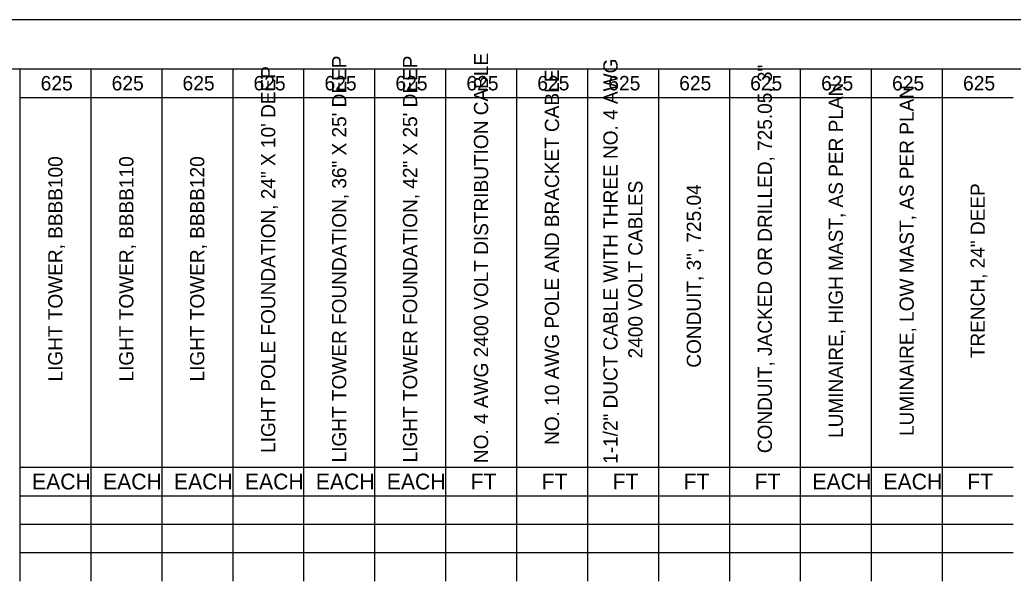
# Model space of a CAD drawing. Extents: x 0 to 34, y 0 to 22.
# Drawn here: x 13.2 to 23.33, y 16.28 to 22 of the extents above; entities that cross this region are included whole.
import ezdxf

# ---------------------------------------------------------------- set-up
doc = ezdxf.new("R2010")
doc.units = 0
for name, color, linetype in [('Default', 7, 'Continuous'), ('SH_Border', 7, 'Continuous'), ('SH_Cut_Line', 7, 'Continuous')]:
    doc.layers.add(name, color=color, linetype=linetype)

msp = doc.modelspace()

# ---------------------------------------------------------------- linework, layer by layer
at = {"layer": 'Default'}
for p, q in [((13.2, 21.5), (13.924, 21.5)), ((13.2, 21.5), (13.2, 21.21)), ((13.924, 21.5), (14.647, 21.5)), ((13.924, 21.5), (13.924, 21.21)), ((14.647, 21.5), (15.371, 21.5)), ((14.647, 21.5), (14.647, 21.21)), ((15.371, 21.5), (16.818, 21.5)), ((15.371, 21.5), (15.371, 21.21)), ((16.094, 21.5), (16.094, 21.21)), ((16.818, 21.5), (23.33, 21.5)), ((16.818, 21.5), (16.818, 21.21)), ((17.541, 21.5), (17.541, 21.21)), ((18.265, 21.5), (18.265, 21.21)), ((18.989, 21.5), (18.989, 21.21)), ((19.712, 21.5), (19.712, 21.21)), ((20.436, 21.5), (20.436, 21.21)), ((21.159, 21.5), (21.159, 21.21)), ((21.883, 21.5), (21.883, 21.21)), ((22.606, 21.5), (22.606, 21.21)), ((13.2, 21.21), (13.924, 21.21)), ((13.2, 21.21), (13.2, 20.92)), ((13.924, 21.21), (14.647, 21.21)), ((13.924, 21.21), (13.924, 20.92)), ((14.647, 21.21), (15.371, 21.21)), ((14.647, 21.21), (14.647, 20.92)), ((15.371, 21.21), (16.818, 21.21)), ((15.371, 21.21), (15.371, 20.92)), ((16.094, 21.21), (16.094, 20.92)), ((16.818, 21.21), (23.33, 21.21)), ((16.818, 21.21), (16.818, 20.92)), ((17.541, 21.21), (17.541, 20.92)), ((18.265, 21.21), (18.265, 20.92)), ((18.989, 21.21), (18.989, 20.92)), ((19.712, 21.21), (19.712, 20.92)), ((20.436, 21.21), (20.436, 20.92)), ((21.159, 21.21), (21.159, 20.92)), ((21.883, 21.21), (21.883, 20.92)), ((22.606, 21.21), (22.606, 20.92)), ((13.2, 20.92), (13.2, 20.63)), ((13.924, 20.92), (13.924, 20.63)), ((14.647, 20.92), (14.647, 20.63)), ((15.371, 20.92), (15.371, 20.63)), ((16.094, 20.92), (16.094, 20.63)), ((16.818, 20.92), (16.818, 20.63)), ((17.541, 20.92), (17.541, 20.63)), ((18.265, 20.92), (18.265, 20.63)), ((18.989, 20.92), (18.989, 20.63)), ((19.712, 20.92), (19.712, 20.63)), ((20.436, 20.92), (20.436, 20.63)), ((21.159, 20.92), (21.159, 20.63)), ((21.883, 20.92), (21.883, 20.63)), ((22.606, 20.92), (22.606, 20.63)), ((13.2, 20.63), (13.2, 20.339)), ((13.924, 20.63), (13.924, 20.339)), ((14.647, 20.63), (14.647, 20.339)), ((15.371, 20.63), (15.371, 20.339)), ((16.094, 20.63), (16.094, 20.339)), ((16.818, 20.63), (16.818, 20.339)), ((17.541, 20.63), (17.541, 20.339)), ((18.265, 20.63), (18.265, 20.339)), ((18.989, 20.63), (18.989, 20.339)), ((19.712, 20.63), (19.712, 20.339)), ((20.436, 20.63), (20.436, 20.339)), ((21.159, 20.63), (21.159, 20.339)), ((21.883, 20.63), (21.883, 20.339)), ((22.606, 20.63), (22.606, 20.339)), ((13.2, 20.339), (13.2, 20.049)), ((13.924, 20.339), (13.924, 20.049)), ((14.647, 20.339), (14.647, 20.049)), ((15.371, 20.339), (15.371, 20.049)), ((16.094, 20.339), (16.094, 20.049)), ((16.818, 20.339), (16.818, 20.049)), ((17.541, 20.339), (17.541, 20.049)), ((18.265, 20.339), (18.265, 20.049)), ((18.989, 20.339), (18.989, 20.049)), ((19.712, 20.339), (19.712, 20.049)), ((20.436, 20.339), (20.436, 20.049)), ((21.159, 20.339), (21.159, 20.049)), ((21.883, 20.339), (21.883, 20.049)), ((22.606, 20.339), (22.606, 20.049)), ((13.2, 20.049), (13.2, 19.759)), ((13.924, 20.049), (13.924, 19.759)), ((14.647, 20.049), (14.647, 19.759)), ((15.371, 20.049), (15.371, 19.759)), ((16.094, 20.049), (16.094, 19.759)), ((16.818, 20.049), (16.818, 19.759)), ((17.541, 20.049), (17.541, 19.759)), ((18.265, 20.049), (18.265, 19.759)), ((18.989, 20.049), (18.989, 19.759)), ((19.712, 20.049), (19.712, 19.759)), ((20.436, 20.049), (20.436, 19.759)), ((21.159, 20.049), (21.159, 19.759)), ((21.883, 20.049), (21.883, 19.759)), ((22.606, 20.049), (22.606, 19.759)), ((13.2, 19.759), (13.2, 19.469)), ((13.924, 19.759), (13.924, 19.469)), ((14.647, 19.759), (14.647, 19.469)), ((15.371, 19.759), (15.371, 19.469)), ((16.094, 19.759), (16.094, 19.469)), ((16.818, 19.759), (16.818, 19.469)), ((17.541, 19.759), (17.541, 19.469)), ((18.265, 19.759), (18.265, 19.469)), ((18.989, 19.759), (18.989, 19.469)), ((19.712, 19.759), (19.712, 19.469)), ((20.436, 19.759), (20.436, 19.469)), ((21.159, 19.759), (21.159, 19.469)), ((21.883, 19.759), (21.883, 19.469)), ((22.606, 19.759), (22.606, 19.469)), ((13.2, 19.469), (13.2, 19.179)), ((13.924, 19.469), (13.924, 19.179)), ((14.647, 19.469), (14.647, 19.179)), ((15.371, 19.469), (15.371, 19.179)), ((16.094, 19.469), (16.094, 19.179)), ((16.818, 19.469), (16.818, 19.179)), ((17.541, 19.469), (17.541, 19.179)), ((18.265, 19.469), (18.265, 19.179)), ((18.989, 19.469), (18.989, 19.179)), ((19.712, 19.469), (19.712, 19.179)), ((20.436, 19.469), (20.436, 19.179)), ((21.159, 19.469), (21.159, 19.179)), ((21.883, 19.469), (21.883, 19.179)), ((22.606, 19.469), (22.606, 19.179)), ((13.2, 19.179), (13.2, 18.889)), ((13.924, 19.179), (13.924, 18.889)), ((14.647, 19.179), (14.647, 18.889)), ((15.371, 19.179), (15.371, 18.889)), ((16.094, 19.179), (16.094, 18.889)), ((16.818, 19.179), (16.818, 18.889)), ((17.541, 19.179), (17.541, 18.889)), ((18.265, 19.179), (18.265, 18.889)), ((18.989, 19.179), (18.989, 18.889)), ((19.712, 19.179), (19.712, 18.889)), ((20.436, 19.179), (20.436, 18.889)), ((21.159, 19.179), (21.159, 18.889)), ((21.883, 19.179), (21.883, 18.889)), ((22.606, 19.179), (22.606, 18.889)), ((13.2, 18.889), (13.2, 18.599)), ((13.924, 18.889), (13.924, 18.599)), ((14.647, 18.889), (14.647, 18.599)), ((15.371, 18.889), (15.371, 18.599)), ((16.094, 18.889), (16.094, 18.599)), ((16.818, 18.889), (16.818, 18.599)), ((17.541, 18.889), (17.541, 18.599)), ((18.265, 18.889), (18.265, 18.599)), ((18.989, 18.889), (18.989, 18.599)), ((19.712, 18.889), (19.712, 18.599)), ((20.436, 18.889), (20.436, 18.599)), ((21.159, 18.889), (21.159, 18.599)), ((21.883, 18.889), (21.883, 18.599)), ((22.606, 18.889), (22.606, 18.599)), ((13.2, 18.599), (13.2, 18.308)), ((13.924, 18.599), (13.924, 18.308)), ((14.647, 18.599), (14.647, 18.308)), ((15.371, 18.599), (15.371, 18.308)), ((16.094, 18.599), (16.094, 18.308)), ((16.818, 18.599), (16.818, 18.308)), ((17.541, 18.599), (17.541, 18.308)), ((18.265, 18.599), (18.265, 18.308)), ((18.989, 18.599), (18.989, 18.308)), ((19.712, 18.599), (19.712, 18.308)), ((20.436, 18.599), (20.436, 18.308)), ((21.159, 18.599), (21.159, 18.308)), ((21.883, 18.599), (21.883, 18.308)), ((22.606, 18.599), (22.606, 18.308)), ((13.2, 18.308), (13.2, 18.018)), ((13.924, 18.308), (13.924, 18.018)), ((14.647, 18.308), (14.647, 18.018)), ((15.371, 18.308), (15.371, 18.018)), ((16.094, 18.308), (16.094, 18.018)), ((16.818, 18.308), (16.818, 18.018)), ((17.541, 18.308), (17.541, 18.018)), ((18.265, 18.308), (18.265, 18.018)), ((18.989, 18.308), (18.989, 18.018)), ((19.712, 18.308), (19.712, 18.018)), ((20.436, 18.308), (20.436, 18.018)), ((21.159, 18.308), (21.159, 18.018)), ((21.883, 18.308), (21.883, 18.018)), ((22.606, 18.308), (22.606, 18.018)), ((13.2, 18.018), (13.2, 17.728)), ((13.924, 18.018), (13.924, 17.728)), ((14.647, 18.018), (14.647, 17.728)), ((15.371, 18.018), (15.371, 17.728)), ((16.094, 18.018), (16.094, 17.728)), ((16.818, 18.018), (16.818, 17.728)), ((17.541, 18.018), (17.541, 17.728)), ((18.265, 18.018), (18.265, 17.728)), ((18.989, 18.018), (18.989, 17.728)), ((19.712, 18.018), (19.712, 17.728)), ((20.436, 18.018), (20.436, 17.728)), ((21.159, 18.018), (21.159, 17.728)), ((21.883, 18.018), (21.883, 17.728)), ((22.606, 18.018), (22.606, 17.728)), ((13.2, 17.728), (13.2, 17.438)), ((13.924, 17.728), (13.924, 17.438)), ((14.647, 17.728), (14.647, 17.438)), ((15.371, 17.728), (15.371, 17.438)), ((16.094, 17.728), (16.094, 17.438)), ((16.818, 17.728), (16.818, 17.438)), ((17.541, 17.728), (17.541, 17.438)), ((18.265, 17.728), (18.265, 17.438)), ((18.989, 17.728), (18.989, 17.438)), ((19.712, 17.728), (19.712, 17.438)), ((20.436, 17.728), (20.436, 17.438)), ((21.159, 17.728), (21.159, 17.438)), ((21.883, 17.728), (21.883, 17.438)), ((22.606, 17.728), (22.606, 17.438)), ((13.2, 17.438), (13.924, 17.438)), ((13.2, 17.438), (13.2, 17.148)), ((13.924, 17.438), (14.647, 17.438)), ((13.924, 17.438), (13.924, 17.148)), ((14.647, 17.438), (15.371, 17.438)), ((14.647, 17.438), (14.647, 17.148)), ((15.371, 17.438), (16.818, 17.438)), ((15.371, 17.438), (15.371, 17.148)), ((16.094, 17.438), (16.094, 17.148)), ((16.818, 17.438), (23.33, 17.438)), ((16.818, 17.438), (16.818, 17.148)), ((17.541, 17.438), (17.541, 17.148)), ((18.265, 17.438), (18.265, 17.148)), ((18.989, 17.438), (18.989, 17.148)), ((19.712, 17.438), (19.712, 17.148)), ((20.436, 17.438), (20.436, 17.148)), ((21.159, 17.438), (21.159, 17.148)), ((21.883, 17.438), (21.883, 17.148)), ((22.606, 17.438), (22.606, 17.148)), ((13.2, 17.148), (13.924, 17.148)), ((13.2, 17.148), (13.2, 16.858)), ((13.924, 17.148), (14.647, 17.148)), ((13.924, 17.148), (13.924, 16.858)), ((14.647, 17.148), (15.371, 17.148)), ((14.647, 17.148), (14.647, 16.858)), ((15.371, 17.148), (16.818, 17.148)), ((15.371, 17.148), (15.371, 16.858)), ((16.094, 17.148), (16.094, 16.858)), ((16.818, 17.148), (23.33, 17.148)), ((16.818, 17.148), (16.818, 16.858)), ((17.541, 17.148), (17.541, 16.858)), ((18.265, 17.148), (18.265, 16.858)), ((18.989, 17.148), (18.989, 16.858)), ((19.712, 17.148), (19.712, 16.858)), ((20.436, 17.148), (20.436, 16.858)), ((21.159, 17.148), (21.159, 16.858)), ((21.883, 17.148), (21.883, 16.858)), ((22.606, 17.148), (22.606, 16.858)), ((13.2, 16.858), (13.924, 16.858)), ((13.2, 16.858), (13.2, 16.568)), ((13.924, 16.858), (14.647, 16.858)), ((13.924, 16.858), (13.924, 16.568)), ((14.647, 16.858), (15.371, 16.858)), ((14.647, 16.858), (14.647, 16.568)), ((15.371, 16.858), (16.818, 16.858)), ((15.371, 16.858), (15.371, 16.568)), ((16.094, 16.858), (16.094, 16.568)), ((16.818, 16.858), (23.33, 16.858)), ((16.818, 16.858), (16.818, 16.568)), ((17.541, 16.858), (17.541, 16.568)), ((18.265, 16.858), (18.265, 16.568)), ((18.989, 16.858), (18.989, 16.568)), ((19.712, 16.858), (19.712, 16.568)), ((20.436, 16.858), (20.436, 16.568)), ((21.159, 16.858), (21.159, 16.568)), ((21.883, 16.858), (21.883, 16.568)), ((22.606, 16.858), (22.606, 16.568)), ((13.2, 16.568), (13.924, 16.568)), ((13.2, 16.568), (13.2, 16.278)), ((13.924, 16.568), (14.647, 16.568)), ((13.924, 16.568), (13.924, 16.278)), ((14.647, 16.568), (15.371, 16.568)), ((14.647, 16.568), (14.647, 16.278)), ((15.371, 16.568), (16.818, 16.568)), ((15.371, 16.568), (15.371, 16.278)), ((16.094, 16.568), (16.094, 16.278)), ((16.818, 16.568), (23.33, 16.568)), ((16.818, 16.568), (16.818, 16.278)), ((17.541, 16.568), (17.541, 16.278)), ((18.265, 16.568), (18.265, 16.278)), ((18.989, 16.568), (18.989, 16.278)), ((19.712, 16.568), (19.712, 16.278)), ((20.436, 16.568), (20.436, 16.278)), ((21.159, 16.568), (21.159, 16.278)), ((21.883, 16.568), (21.883, 16.278)), ((22.606, 16.568), (22.606, 16.278))]:
    msp.add_line(p, q, dxfattribs=at)
at = {"layer": 'SH_Border'}
msp.add_lwpolyline([(1.5, 21.5), (33.5, 21.5), (33.5, 0.5), (1.5, 0.5)], close=True, dxfattribs=at)
at = {"layer": 'SH_Cut_Line'}
msp.add_lwpolyline([(0, 0), (34, 0), (34, 22), (0, 22)], close=True, dxfattribs=at)

# ---------------------------------------------------------------- texts
at = {"layer": 'Default'}
for s, p in [('LIGHT TOWER FOUNDATION, 36" X 25\' DEEP', (16.529, 17.488)), ('LIGHT TOWER FOUNDATION, 42" X 25\' DEEP', (17.252, 17.488)), ('NO. 4 AWG 2400 VOLT DISTRIBUTION CABLE', (17.976, 17.481)), ('1-1/2" DUCT CABLE WITH THREE NO. 4 AWG ', (19.296, 17.473)), ('LIGHT POLE FOUNDATION, 24" X 10\' DEEP', (15.805, 17.585)), ('NO. 10 AWG POLE AND BRACKET CABLE', (18.699, 17.666)), ('CONDUIT, JACKED OR DRILLED, 725.05, 3"', (20.87, 17.582)), ('LUMINAIRE, HIGH MAST, AS PER PLAN', (21.594, 17.738)), ('LUMINAIRE, LOW MAST, AS PER PLAN', (22.317, 17.757)), ('LIGHT TOWER, BBBB100', (13.634, 18.313)), ('LIGHT TOWER, BBBB110', (14.358, 18.313)), ('LIGHT TOWER, BBBB120', (15.081, 18.313)), ('2400 VOLT CABLES', (19.55, 18.549)), ('CONDUIT, 3", 725.04', (20.146, 18.454)), ('TRENCH, 24" DEEP', (23.041, 18.551))]:
    msp.add_text(s, height=0.14506, rotation=90, dxfattribs=at).set_placement(p)
for s, height, p in [('625', 0.1468, (13.412, 21.281)), ('625', 0.1468, (14.136, 21.281)), ('625', 0.1468, (14.859, 21.281)), ('625', 0.1468, (15.583, 21.281)), ('625', 0.1468, (16.307, 21.281)), ('625', 0.1468, (17.03, 21.281)), ('625', 0.1468, (17.754, 21.281)), ('625', 0.1468, (18.477, 21.281)), ('625', 0.1468, (19.201, 21.281)), ('625', 0.1468, (19.924, 21.281)), ('625', 0.1468, (20.648, 21.281)), ('625', 0.1468, (21.372, 21.281)), ('625', 0.1468, (22.095, 21.281)), ('625', 0.1468, (22.819, 21.281)), ('EACH', 0.1615, (13.324, 17.212)), ('EACH', 0.1615, (14.048, 17.212)), ('EACH', 0.1615, (14.771, 17.212)), ('EACH', 0.1615, (15.495, 17.212)), ('EACH', 0.1615, (16.218, 17.212)), ('EACH', 0.1615, (16.942, 17.212)), ('FT', 0.1615, (17.797, 17.212)), ('FT', 0.1615, (18.521, 17.212)), ('FT', 0.1615, (19.245, 17.212)), ('FT', 0.1615, (19.968, 17.212)), ('FT', 0.1615, (20.692, 17.212)), ('EACH', 0.1615, (21.283, 17.212)), ('EACH', 0.1615, (22.007, 17.212)), ('FT', 0.1615, (22.862, 17.212))]:
    msp.add_text(s, height=height, dxfattribs=at).set_placement(p)

doc.saveas('drawing.dxf')
